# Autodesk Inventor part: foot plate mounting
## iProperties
Shininess: 64.0
Length Units: 11269
Angle Units: 11279
Time Units: 11290
Mass Units: 11283
Length Display Precision: 3
Angle Display Precision: 2
Compacted: True
Part Number: foot plate mounting
Document SubType Name: Sheet Metal
Created: 2002-11
Designer: Elise Moss
Density: 0.0
Volumn: 0.0
Area: 0.0
PropertySet Name: Model Information
Control State: 0
Master: False
Checked Out: False
Author: Elise Moss
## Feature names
1. Plate1
2. Cut1
